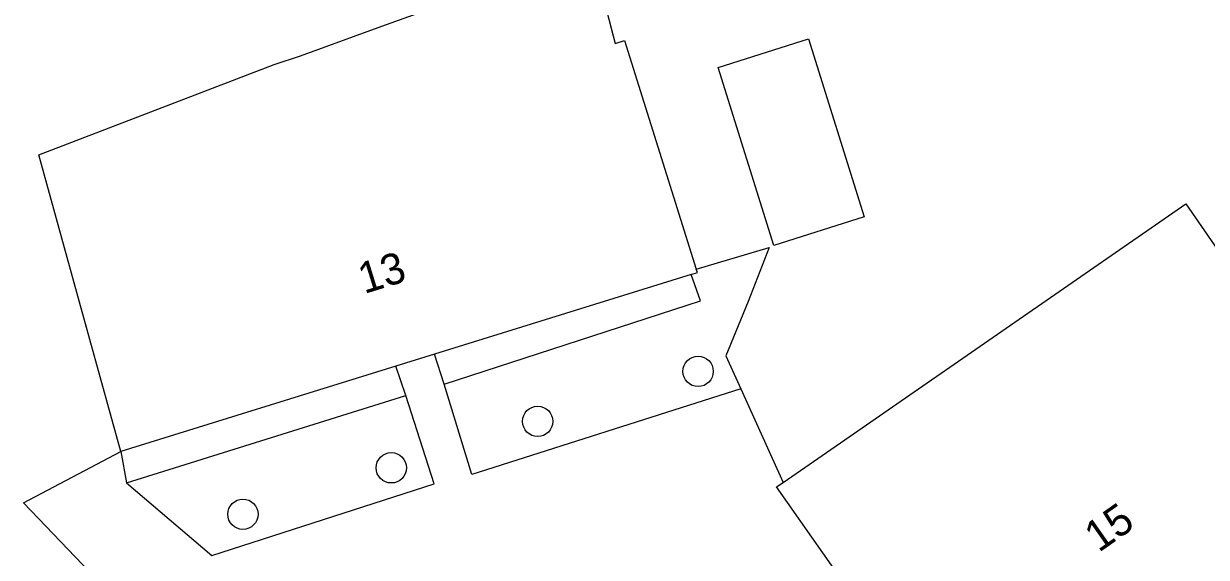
# Model space of a CAD drawing. Extents: x 162880 to 165536, y 384011 to 385179.
# Drawn here: x 164189.38 to 164227.48, y 384327.85 to 384345.04 of the extents above; entities that cross this region are included whole.
import ezdxf

# ---------------------------------------------------------------- set-up
doc = ezdxf.new("R2010")
doc.units = 0
for name, color, linetype in [('IMGEO_Boom', 7, 'Continuous'), ('IMGEO_Hek', 7, 'Continuous'), ('IMGEO_Pand', 7, 'Continuous'), ('IMGEO_Pand_nummerreeks', 7, 'Continuous'), ('IMGEO_Rijbaan_lokaal_open', 7, 'Continuous'), ('IMGEO_Terreindeel_halfverhard', 7, 'Continuous'), ('IMGEO_Terreindeel_onvherhard', 7, 'Continuous')]:
    doc.layers.add(name, color=color, linetype=linetype)

msp = doc.modelspace()

# ---------------------------------------------------------------- linework, layer by layer
at = {"layer": 'IMGEO_Boom'}
for centre in [(164211.105, 384333.838), (164205.937, 384332.227), (164201.221, 384330.731), (164196.441, 384329.235)]:
    msp.add_circle(centre, 0.489, dxfattribs=at)
at = {"layer": 'IMGEO_Hek'}
msp.add_lwpolyline([(164194.961, 384321.055), (164193.903, 384324.871), (164189.377, 384329.607)], dxfattribs=at)
at = {"layer": 'IMGEO_Pand'}
for points in [[(164192.51, 384331.254), (164191.177, 384336.073), (164189.865, 384340.814), (164197.444, 384343.723), (164198.294, 384344.01), (164200.915, 384344.959), (164202.802, 384345.642), (164202.678, 384346.022), (164203.127, 384346.168), (164203.25, 384345.788), (164204.723, 384346.268), (164204.573, 384346.639), (164204.995, 384346.81), (164205.145, 384346.439), (164206.731, 384347.003), (164206.573, 384347.592), (164207.112, 384347.737), (164207.255, 384347.111), (164207.705, 384347.211), (164208.438, 384344.404), (164208.733, 384344.497), (164209.583, 384341.792), (164211.048, 384337.129)], [(164214.658, 384344.549), (164216.46, 384338.813), (164213.55, 384337.898), (164211.748, 384343.634), (164214.658, 384344.549)], [(164213.844, 384330.259), (164226.813, 384339.238), (164229.747, 384334.996), (164230.475, 384333.944)], [(164210.884, 384336.961), (164202.612, 384334.391)], [(164210.884, 384336.961), (164211.082, 384337.022), (164211.048, 384337.129)], [(164202.612, 384334.391), (164201.371, 384334.006)], [(164201.371, 384334.006), (164192.51, 384331.254)], [(164218.506, 384323.135), (164216.614, 384325.869), (164213.634, 384330.114), (164213.844, 384330.259)]]:
    msp.add_lwpolyline(points, dxfattribs=at)
at = {"layer": 'IMGEO_Rijbaan_lokaal_open'}
for points in [[(164202.923, 384333.426), (164202.612, 384334.391)], [(164201.693, 384333.063), (164201.371, 384334.006)], [(164212.479, 384333.28), (164203.816, 384330.52), (164202.923, 384333.426)], [(164192.693, 384330.245), (164195.444, 384327.906), (164202.605, 384330.213), (164201.693, 384333.063)], [(164212.479, 384333.28), (164213.844, 384330.259)], [(164194.961, 384321.055), (164193.903, 384324.871), (164189.377, 384329.607), (164192.51, 384331.254)], [(164192.51, 384331.254), (164192.693, 384330.245)]]:
    msp.add_lwpolyline(points, dxfattribs=at)
at = {"layer": 'IMGEO_Terreindeel_halfverhard'}
for points in [[(164202.923, 384333.426), (164211.182, 384336.114), (164210.884, 384336.961)], [(164192.693, 384330.245), (164201.693, 384333.063)]]:
    msp.add_lwpolyline(points, dxfattribs=at)
at = {"layer": 'IMGEO_Terreindeel_onvherhard'}
msp.add_lwpolyline([(164211.048, 384337.129), (164213.396, 384337.828), (164212.717, 384336.087), (164212.001, 384334.337), (164212.479, 384333.28)], dxfattribs=at)

# ---------------------------------------------------------------- texts
at = {"layer": 'IMGEO_Pand_nummerreeks'}
for s, rotation, p in [('13', 17.2518, (164200.346, 384336.327)), ('15', 35.0249, (164224.012, 384327.985))]:
    msp.add_text(s, height=1, rotation=rotation, dxfattribs=at).set_placement(p)

doc.saveas('drawing.dxf')
